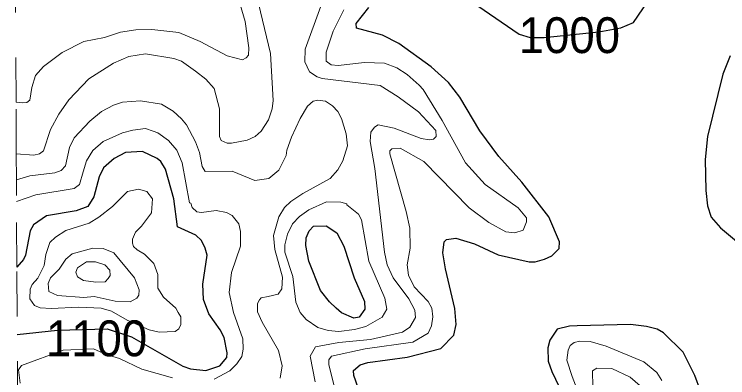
# Model space of a CAD drawing. Extents: x 423 to 448.8, y 7456.3 to 7484.
# Drawn here: x 423.04 to 424.633, y 7473.353 to 7474.164 of the extents above; entities that cross this region are included whole.
import ezdxf
from ezdxf.enums import TextEntityAlignment as Align

# ---------------------------------------------------------------- set-up
doc = ezdxf.new("R2010")
doc.units = 0
doc.header["$LTSCALE"] = 0.032
doc.linetypes.add('SHORT_DASHED', pattern=[2.7, 1.5, -1.2])
for name, color, linetype, lineweight in [('1', 7, 'Continuous', 25), ('2', 7, 'Continuous', 13), ('22', 7, 'SHORT_DASHED', 13)]:
    doc.layers.add(name, color=color, linetype=linetype, lineweight=lineweight)
doc.layers.add('61', color=7, linetype='Continuous')

msp = doc.modelspace()

# ---------------------------------------------------------------- linework, layer by layer
at = {"layer": '1'}
for points in [[(424.0752, 7474.183), (424.1672, 7474.1204), (424.1919, 7474.1127), (424.2226, 7474.1124), (424.3448, 7474.1251), (424.3938, 7474.1339), (424.4227, 7474.1463), (424.4658, 7474.2101)], [(423.8129, 7473.316), (423.7982, 7473.3578), (423.7975, 7473.3694), (423.8122, 7473.3817), (423.8292, 7473.3872), (423.9174, 7473.3988), (423.9924, 7473.4181), (424.021, 7473.4482), (424.0264, 7473.4722), (424.0233, 7473.5078), (424.0024, 7473.596), (423.997, 7473.6316), (423.9993, 7473.6563), (424.0048, 7473.6617), (424.0256, 7473.6648), (424.0674, 7473.6517), (424.12, 7473.6277), (424.1896, 7473.6122), (424.2027, 7473.6122), (424.2237, 7473.6176), (424.2399, 7473.6254), (424.2561, 7473.6416), (424.2569, 7473.6563), (424.2337, 7473.712), (424.1734, 7473.7894), (424.1216, 7473.8473), (424.079, 7473.9046), (424.0349, 7473.9796), (424.0094, 7474.0121), (423.9707, 7474.0469), (423.8988, 7474.0995), (423.8617, 7474.118), (423.8037, 7474.1335), (423.8029, 7474.1436), (423.8315, 7474.1799)], [(424.6382, 7474.0717), (424.622, 7474.0307), (424.588, 7473.8915), (424.5825, 7473.8404), (424.5841, 7473.7708), (424.588, 7473.7368), (424.5957, 7473.7112), (424.6165, 7473.688), (424.6746, 7473.6393)], [(423.0464, 7473.45), (423.1361, 7473.459), (423.2475, 7473.462), (423.3012, 7473.4445), (423.4162, 7473.3786), (423.4332, 7473.3732), (423.4672, 7473.3693), (423.4989, 7473.3794), (423.5144, 7473.398), (423.5152, 7473.4088), (423.5082, 7473.4429), (423.4997, 7473.4599), (423.4741, 7473.4954), (423.4626, 7473.5279), (423.461, 7473.562), (423.4703, 7473.6269), (423.4664, 7473.6424), (423.4579, 7473.6594), (423.4455, 7473.671), (423.4045, 7473.6896), (423.3961, 7473.7522), (423.3775, 7473.8188), (423.3674, 7473.8358), (423.3589, 7473.8427), (423.3264, 7473.8582), (423.2885, 7473.8558), (423.263, 7473.8427), (423.239, 7473.8218), (423.229, 7473.8017), (423.2174, 7473.7569), (423.2042, 7473.7352), (423.1779, 7473.7259), (423.1114, 7473.7143), (423.0828, 7473.6942), (423.0751, 7473.6811), (423.065, 7473.6269), (423.0603, 7473.6169), (423.0456, 7473.6)], [(424.5717, 7473.3237), (424.5593, 7473.3578), (424.533, 7473.4104), (424.4897, 7473.4537), (424.475, 7473.4614), (424.4511, 7473.4676), (424.4155, 7473.4722), (424.2964, 7473.4691), (424.2794, 7473.4684), (424.2523, 7473.4614), (424.2353, 7473.4367), (424.2314, 7473.4197), (424.2321, 7473.3902)], [(424.2321, 7473.3902), (424.2399, 7473.3671), (424.2654, 7473.3145)]]:
    msp.add_lwpolyline(points, dxfattribs=at)
msp.add_lwpolyline([(423.7587, 7473.5085), (423.7433, 7473.5225), (423.7232, 7473.548), (423.6977, 7473.613), (423.6907, 7473.6486), (423.6915, 7473.6656), (423.6985, 7473.6811), (423.7077, 7473.6911), (423.7364, 7473.6919), (423.7603, 7473.6764), (423.7758, 7473.647), (423.799, 7473.5759), (423.8215, 7473.5233), (423.8222, 7473.5063), (423.8098, 7473.4885), (423.7983, 7473.4862), (423.7704, 7473.4977)], close=True, dxfattribs=at)
at = {"layer": '2'}
for points in [[(423.5275, 7474.2426), (423.5554, 7474.1483), (423.5639, 7474.0895), (423.5631, 7474.0732), (423.5577, 7474.067), (423.5492, 7474.0631), (423.5152, 7474.0716), (423.4548, 7474.1033), (423.4069, 7474.1235), (423.3466, 7474.1304), (423.311, 7474.1296), (423.2769, 7474.1242), (423.2414, 7474.1127), (423.195, 7474.1034), (423.147, 7474.0794), (423.1052, 7474.0477), (423.0874, 7474.0275), (423.0789, 7474.0013), (423.0743, 7473.9727), (423.0678, 7473.9678), (423.0588, 7473.9665), (423.0437, 7473.9682)], [(423.5848, 7474.1885), (423.6118, 7474.0771), (423.618, 7473.9719), (423.6157, 7473.9533), (423.6072, 7473.9286), (423.5909, 7473.9038), (423.5778, 7473.8915), (423.56, 7473.8837), (423.5245, 7473.8767), (423.5152, 7473.8767), (423.502, 7473.8829), (423.4982, 7473.8915), (423.4982, 7473.9533), (423.4858, 7473.9989), (423.4672, 7474.0198), (423.4448, 7474.0376), (423.4131, 7474.06), (423.3961, 7474.0655), (423.3326, 7474.0763)], [(423.7116, 7473.3439), (423.7008, 7473.4011), (423.7124, 7473.4219), (423.7642, 7473.432), (423.8354, 7473.4382), (423.9065, 7473.4552), (423.9228, 7473.466), (423.9359, 7473.4877), (423.9344, 7473.5039), (423.9205, 7473.5295), (423.8856, 7473.5759), (423.8725, 7473.6053), (423.8663, 7473.6331), (423.8447, 7473.8203), (423.8346, 7473.8806), (423.8361, 7473.9015), (423.8439, 7473.9123), (423.8524, 7473.9178), (423.888, 7473.91), (423.9483, 7473.8868), (423.9669, 7473.8845), (423.9762, 7473.886), (423.9815, 7473.8914), (423.9808, 7473.9053), (423.9421, 7473.9464), (423.8973, 7473.9804), (423.857, 7474.0051), (423.7271, 7474.0214), (423.7162, 7474.0245), (423.6992, 7474.0361), (423.6884, 7474.0585), (423.6892, 7474.0864), (423.724, 7474.1823)], [(423.9011, 7473.8659), (423.9545, 7473.8357), (424.0558, 7473.7321), (424.0991, 7473.6996), (424.137, 7473.6787), (424.1571, 7473.6764), (424.1757, 7473.6826), (424.1834, 7473.7012), (424.1834, 7473.7097), (424.1649, 7473.7321), (424.0914, 7473.7847), (424.0473, 7473.8327), (423.9955, 7473.927), (423.9529, 7473.9967), (423.9437, 7474.0059), (423.9174, 7474.0299), (423.8942, 7474.0446), (423.8663, 7474.0554), (423.8215, 7474.0569), (423.7627, 7474.05), (423.7472, 7474.0516), (423.7364, 7474.06), (423.7364, 7474.0802), (423.7518, 7474.1266), (423.7758, 7474.1745)], [(423.3326, 7474.0763), (423.2955, 7474.0701), (423.2615, 7474.0554), (423.2065, 7474.0206), (423.1617, 7473.9734), (423.1393, 7473.9417), (423.1207, 7473.9069), (423.1052, 7473.8597), (423.0964, 7473.8531), (423.0836, 7473.8497), (423.0443, 7473.8527)], [(423.6335, 7473.3523), (423.6381, 7473.3794), (423.6296, 7473.4142), (423.5933, 7473.4769), (423.5832, 7473.5001), (423.5832, 7473.5187), (423.5871, 7473.5271), (423.5909, 7473.5318), (423.6064, 7473.5341), (423.6288, 7473.5395), (423.6374, 7473.5519), (423.6389, 7473.5774), (423.6219, 7473.6393), (423.6188, 7473.6703), (423.6304, 7473.712), (423.6428, 7473.7329), (423.6575, 7473.7468), (423.6838, 7473.7646), (423.7449, 7473.7979), (423.7619, 7473.8172), (423.7735, 7473.8373), (423.7835, 7473.8706), (423.7812, 7473.8976), (423.7704, 7473.9316), (423.7619, 7473.9471), (423.7503, 7473.9603), (423.7348, 7473.9703), (423.7178, 7473.9726), (423.707, 7473.9703), (423.6946, 7473.9595), (423.6783, 7473.9317), (423.659, 7473.8899), (423.6482, 7473.8613), (423.6467, 7473.8489), (423.6304, 7473.8164), (423.608, 7473.7978), (423.5771, 7473.7932), (423.526, 7473.8141), (423.4664, 7473.8133), (423.4595, 7473.8249), (423.4533, 7473.8559), (423.4448, 7473.8798), (423.4246, 7473.9178), (423.4131, 7473.9309), (423.3945, 7473.9479), (423.3682, 7473.9641), (423.3218, 7473.9711), (423.2816, 7473.968), (423.2615, 7473.9618), (423.2344, 7473.9471), (423.2088, 7473.9255), (423.1733, 7473.8884), (423.1632, 7473.8667), (423.1539, 7473.8265), (423.1447, 7473.8157), (423.13, 7473.8102), (423.0743, 7473.804), (423.0446, 7473.795)], [(423.4858, 7473.35), (423.5213, 7473.3686), (423.5368, 7473.384), (423.5476, 7473.4003), (423.5507, 7473.4166), (423.5499, 7473.4398), (423.5291, 7473.4985), (423.5198, 7473.5434), (423.5245, 7473.5883), (423.5446, 7473.647), (423.5446, 7473.6795), (423.5415, 7473.6965), (423.526, 7473.7151), (423.5136, 7473.722), (423.4904, 7473.7267), (423.4579, 7473.722), (423.4471, 7473.7236), (423.437, 7473.7329), (423.4339, 7473.743), (423.4308, 7473.7437), (423.4146, 7473.8327), (423.403, 7473.8613), (423.3844, 7473.8829), (423.3605, 7473.8999), (423.3497, 7473.9038), (423.3326, 7473.9092), (423.3048, 7473.9061), (423.2816, 7473.8999), (423.2383, 7473.8806), (423.2151, 7473.8605), (423.2011, 7473.8373), (423.1934, 7473.8126), (423.1857, 7473.7847), (423.1733, 7473.7754), (423.0882, 7473.7615), (423.0449, 7473.7462)], [(423.7541, 7473.3346), (423.7418, 7473.3825), (423.7418, 7473.3934), (423.748, 7473.401), (423.823, 7473.4173), (423.9298, 7473.4328), (423.9638, 7473.4529), (423.9715, 7473.4691), (423.9746, 7473.4893), (423.9723, 7473.5086), (423.9637, 7473.5233), (423.9328, 7473.5558), (423.9197, 7473.5821), (423.9173, 7473.6053), (423.9236, 7473.6424), (423.9228, 7473.6873), (423.915, 7473.7244), (423.8787, 7473.8528), (423.8787, 7473.8597), (423.8825, 7473.8644), (423.9011, 7473.8659)], [(424.4858, 7473.3469), (424.4743, 7473.3647), (424.4456, 7473.3887), (424.3613, 7473.4235), (424.3258, 7473.4343), (424.3026, 7473.4351), (424.2902, 7473.432), (424.2809, 7473.4251), (424.2763, 7473.415), (424.2739, 7473.3926), (424.2855, 7473.3562), (424.3087, 7473.2959)], [(423.0526, 7473.3408), (423.0495, 7473.3709), (423.0557, 7473.3802), (423.1488, 7473.4149), (423.2164, 7473.4179), (423.2449, 7473.405), (423.275, 7473.396), (423.3249, 7473.3724), (423.393, 7473.3531)], [(424.3319, 7473.333), (424.3312, 7473.3686), (424.3404, 7473.3747), (424.3737, 7473.374), (424.4147, 7473.3547), (424.4487, 7473.3253)]]:
    msp.add_lwpolyline(points, dxfattribs=at)
for points in [[(423.1191, 7473.6547), (423.1315, 7473.6671), (423.1547, 7473.6818), (423.2073, 7473.6981), (423.2289, 7473.7112), (423.2591, 7473.7352), (423.2924, 7473.7692), (423.3172, 7473.7739), (423.3357, 7473.7692), (423.3481, 7473.7522), (423.3465, 7473.7213), (423.3241, 7473.6911), (423.3102, 7473.6779), (423.304, 7473.6625), (423.304, 7473.6532), (423.3063, 7473.6462), (423.314, 7473.6385), (423.3303, 7473.6292), (423.3512, 7473.6083), (423.3605, 7473.5836), (423.3605, 7473.5534), (423.3728, 7473.5333), (423.4007, 7473.5086), (423.4061, 7473.4985), (423.4115, 7473.4893), (423.4115, 7473.4722), (423.4069, 7473.4622), (423.3991, 7473.456), (423.3636, 7473.4552), (423.3411, 7473.4599), (423.2916, 7473.4815), (423.2568, 7473.5016), (423.2336, 7473.5086), (423.1841, 7473.5109), (423.1223, 7473.5078), (423.0975, 7473.5094), (423.0851, 7473.514), (423.0743, 7473.5294), (423.075, 7473.5511), (423.0797, 7473.5612), (423.0921, 7473.5751), (423.1068, 7473.6037), (423.1106, 7473.6285)], [(423.782, 7473.7391), (423.7827, 7473.7414), (423.7689, 7473.7452), (423.7371, 7473.746), (423.6977, 7473.7282), (423.6768, 7473.7128), (423.6613, 7473.6965), (423.6498, 7473.6733), (423.6436, 7473.6501), (423.6436, 7473.6331), (423.6621, 7473.579), (423.6683, 7473.5217), (423.6783, 7473.4985), (423.6915, 7473.4831), (423.7178, 7473.4653), (423.741, 7473.4583), (423.7642, 7473.456), (423.7998, 7473.4606), (423.8246, 7473.4676), (423.8609, 7473.4885), (423.8717, 7473.5063), (423.8671, 7473.531), (423.8315, 7473.613), (423.8153, 7473.7058), (423.8083, 7473.7182)], [(423.2653, 7473.524), (423.2182, 7473.5341), (423.195, 7473.5325), (423.1362, 7473.5364), (423.1168, 7473.5457), (423.1153, 7473.5635), (423.1207, 7473.5759), (423.14, 7473.5952), (423.1547, 7473.6177), (423.1687, 7473.63), (423.2151, 7473.6424), (423.2383, 7473.6416), (423.2622, 7473.6316), (423.3079, 7473.5758), (423.3187, 7473.5496), (423.3179, 7473.5372), (423.3133, 7473.531), (423.2986, 7473.5225)], [(423.1809, 7473.5983), (423.2014, 7473.6116), (423.2214, 7473.6122), (423.242, 7473.6049), (423.2531, 7473.5933), (423.2536, 7473.5816), (423.2497, 7473.5744), (423.2425, 7473.5672), (423.222, 7473.5666), (423.1947, 7473.5705), (423.1809, 7473.5783), (423.1775, 7473.5888)]]:
    msp.add_lwpolyline(points, close=True, dxfattribs=at)
at = {"layer": '22'}
for points in [[(423.0437, 7473.9682), (423.0419, 7474.325), (423.0418, 7474.336), (423.0401, 7474.6804), (423.0398, 7474.7385)], [(423.0456, 7473.6), (423.0448, 7473.7601), (423.0446, 7473.795), (423.0443, 7473.8527), (423.0437, 7473.9682)], [(423.048, 7473.128), (423.0477, 7473.1953), (423.0472, 7473.2901), (423.0456, 7473.6)]]:
    msp.add_lwpolyline(points, dxfattribs=at)

# ---------------------------------------------------------------- texts
at = {"layer": '61', "width": 0.95}
for s, p in [('1000', (424.2792, 7474.0778)), ('1100', (423.2233, 7473.4011))]:
    msp.add_text(s, height=0.08, dxfattribs=at).set_placement(p, align=Align.CENTER)

doc.saveas('drawing.dxf')
